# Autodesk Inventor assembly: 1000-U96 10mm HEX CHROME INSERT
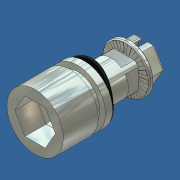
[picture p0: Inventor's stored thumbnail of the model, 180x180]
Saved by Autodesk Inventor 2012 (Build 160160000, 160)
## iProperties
Created: 2007-03
Part Number: 1000-U96 10mm HEX CHROME INSERT
Document SubType Name: Assembly
Designer: Andy Moles
Translation Standard: STEP AP214IS
File Name: 1000-U96_ASM
Preprocessor: PRO/ENGINEER BY PARAMETRIC TECHNOLOGY CORPORATION, 2003200
Postprocessor: Build: 344b, Release: 11 SP2 - Date: Fri 08/18/2006
Sent Units: MILLIMETERS
Uncertainty: 0.0038593728735789997
Author: Andy Moles
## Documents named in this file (4)
- C:\Andys Backup Data\ANDY'S INVENTOR\INVENTOR LIBRARIES\PARTS LIBRARY\HANDLES LOCKS STOPS\SUBCOMPONENTS\EMKA SUBCOMPONENTS\1000-U96 10mm HEX CHROME INSERT.iam
- C:\Andys Backup Data\ANDY'S INVENTOR\INVENTOR LIBRARIES\PARTS LIBRARY\HANDLES LOCKS STOPS\SUBCOMPONENTS\EMKA SUBCOMPONENTS\1000-175.ipt
- C:\Andys Backup Data\ANDY'S INVENTOR\INVENTOR LIBRARIES\PARTS LIBRARY\HANDLES LOCKS STOPS\SUBCOMPONENTS\EMKA SUBCOMPONENTS\1000-277-01_PRT.ipt
- C:\Andys Backup Data\ANDY'S INVENTOR\INVENTOR LIBRARIES\PARTS LIBRARY\HANDLES LOCKS STOPS\SUBCOMPONENTS\EMKA SUBCOMPONENTS\1000-03_PRT.ipt
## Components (3 placed, 3 different names)
1. 1000-03
2. 1000-277-01 — Insert:1
3. 1000-175:1 — Insert:1
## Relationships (1: Insert 1)
- Insert:1: 1000-277-01 ↔ 1000-175:1
